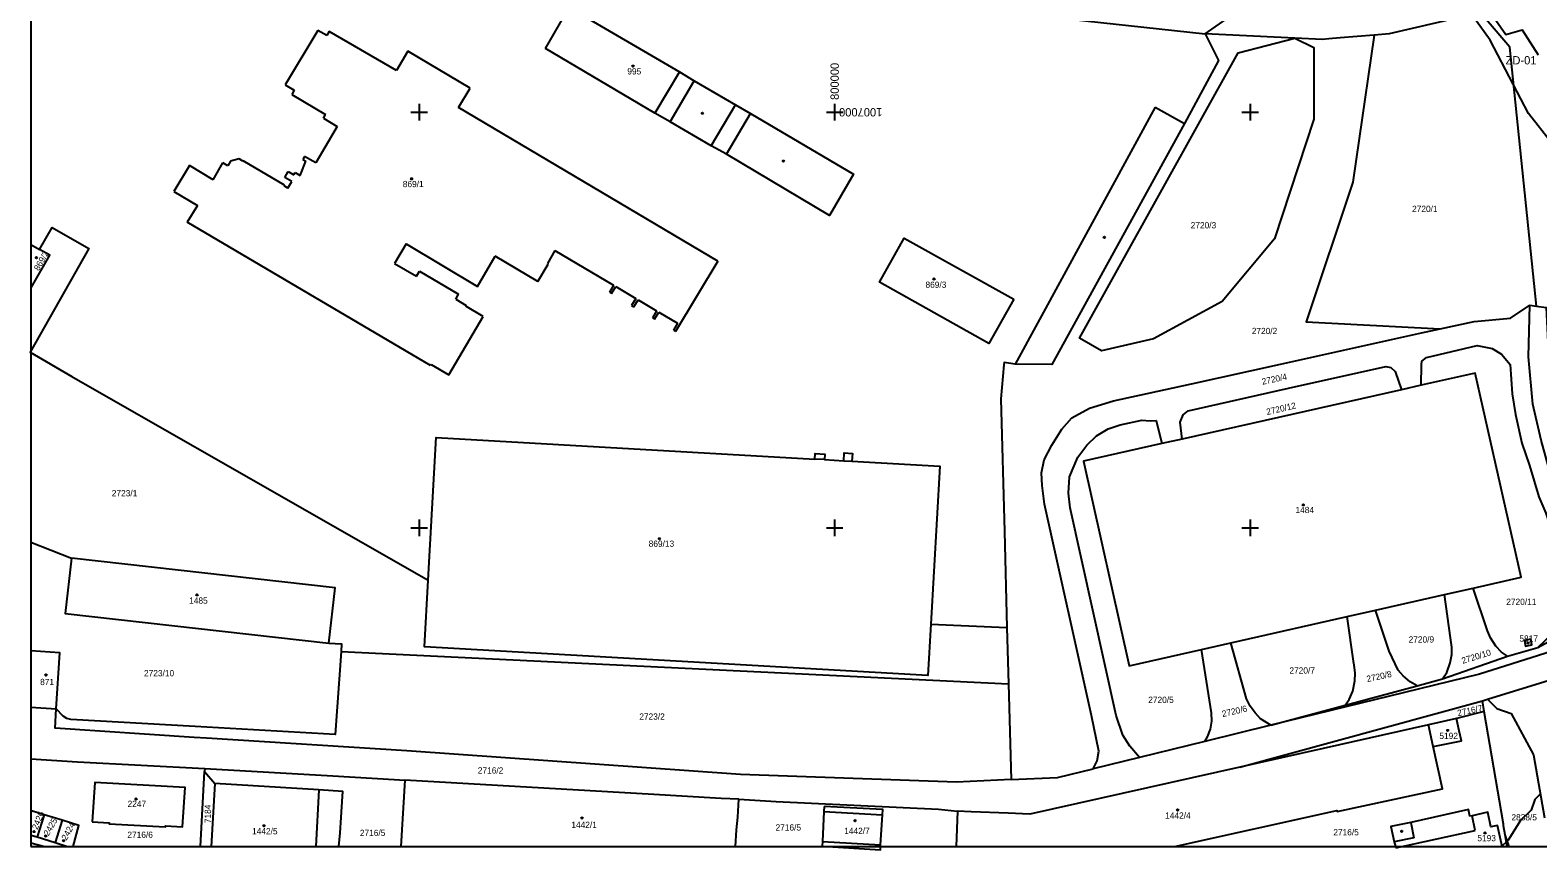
# Model space of a CAD drawing. Extents: x -800194 to -799297, y -1007177 to -1006761.
# Drawn here: x -800193.6 to -799830.8, y -1007177.4 to -1006980.2 of the extents above; entities that cross this region are included whole.
import ezdxf

# ---------------------------------------------------------------- set-up
doc = ezdxf.new("R2010")
doc.units = 0
for name, color, linetype in [('BPEJ', 7, 'Continuous'), ('Dočasné zábory', 7, 'Continuous'), ('Dočasné zábory - čísla', 7, 'Continuous'), ('Legenda 1', 7, 'Continuous'), ('Ramove udaje', 7, 'Continuous'), ('Vrstva 55', 7, 'Continuous'), ('Vrstva 56', 7, 'Continuous'), ('Vrstva 57', 7, 'Continuous'), ('Vrstva 59', 7, 'Continuous')]:
    doc.layers.add(name, color=color, linetype=linetype)

msp = doc.modelspace()

# ---------------------------------------------------------------- linework, layer by layer
at = {"layer": 'BPEJ'}
msp.add_lwpolyline([(-799830.18, -1007163.95), (-799831.53, -1007165.33), (-799832.38, -1007167.87), (-799834.92, -1007170.41), (-799837.89, -1007175.07), (-799838.13, -1007175.29), (-799838.36, -1007175.51), (-799839.39, -1007176.48), (-799839.57, -1007176.65)], dxfattribs=at)
at = {"layer": 'Dočasné zábory'}
for points in [[(-799851.52, -1006962.6), (-799838.48, -1006981.29), (-799834.59, -1006980.15), (-799830.67, -1006986.18)], [(-799827.49, -1007007.33), (-799833.05, -1007000.26), (-799842.29, -1006982.66), (-799850.11, -1006971.65)]]:
    msp.add_lwpolyline(points, dxfattribs=at)
at = {"layer": 'Legenda 1'}
msp.add_lwpolyline([(-800193.4, -1007176.65), (-799312.4, -1007176.65), (-799312.4, -1006766.65), (-800193.4, -1006766.65)], close=True, dxfattribs=at)
at = {"layer": 'Ramove udaje'}
for p, q in [((-800102, -1007000), (-800100, -1007000)), ((-800100, -1006998), (-800100, -1007002)), ((-800100, -1007000), (-800098, -1007000)), ((-800002, -1007000), (-800000, -1007000)), ((-800000, -1006998), (-800000, -1007002)), ((-800000, -1007000), (-799998, -1007000)), ((-799902, -1007000), (-799900, -1007000)), ((-799900, -1006998), (-799900, -1007002)), ((-799900, -1007000), (-799898, -1007000)), ((-800100, -1007098), (-800100, -1007102)), ((-800000, -1007098), (-800000, -1007102)), ((-799900, -1007098), (-799900, -1007102)), ((-800102, -1007100), (-800100, -1007100)), ((-800100, -1007100), (-800098, -1007100)), ((-800002, -1007100), (-800000, -1007100)), ((-800000, -1007100), (-799998, -1007100)), ((-799902, -1007100), (-799900, -1007100)), ((-799900, -1007100), (-799898, -1007100))]:
    msp.add_line(p, q, dxfattribs=at)
at = {"layer": 'Vrstva 55'}
for p, q in [((-799910.85, -1006981.15), (-799905.8, -1006977.56)), ((-799870.16, -1006981.42), (-799878.32, -1006982.12)), ((-799866.6, -1006981.12), (-799870.16, -1006981.42)), ((-799832.71, -1007046.42), (-799831.14, -1007046.62)), ((-799858.8, -1007053.02), (-799854.29, -1007052.07)), ((-799854.29, -1007052.07), (-799846.07, -1007050.35)), ((-799863.56, -1007066.73), (-799916.37, -1007078.61)), ((-799858.84, -1007065.67), (-799863.56, -1007066.73)), ((-799916.37, -1007078.61), (-799921.23, -1007079.7)), ((-799869.87, -1007119.78), (-799853.26, -1007116.03)), ((-799853.26, -1007116.03), (-799846.34, -1007114.47)), ((-799876.63, -1007121.3), (-799869.87, -1007119.78)), ((-799976.85, -1007123.12), (-799958.55, -1007123.98)), ((-799958.55, -1007123.98), (-799958.18, -1007137.5)), ((-799904.64, -1007127.61), (-799876.63, -1007121.3)), ((-799911.69, -1007129.2), (-799904.64, -1007127.61)), ((-800118.77, -1007129.72), (-799958.18, -1007137.5)), ((-799853.69, -1007136.27), (-799838.05, -1007130.83)), ((-799838.05, -1007130.83), (-799830.82, -1007128.75)), ((-799958.18, -1007137.5), (-799957.55, -1007160.54)), ((-799877.13, -1007142.66), (-799859.81, -1007137.94)), ((-799859.81, -1007137.94), (-799853.69, -1007136.27)), ((-799902.49, -1007157.51), (-799844.11, -1007141.59)), ((-799895.02, -1007147.45), (-799877.13, -1007142.66)), ((-799844.11, -1007141.59), (-799842.89, -1007141.21)), ((-799843.67, -1007144.18), (-799844.11, -1007141.59)), ((-799842.89, -1007141.21), (-799840.66, -1007143.43)), ((-800193.4, -1007143.13), (-800187.33, -1007143.52)), ((-799850.35, -1007145.84), (-799857.1, -1007147.35)), ((-799843.67, -1007144.18), (-799850.35, -1007145.84)), ((-799895.02, -1007147.45), (-799910.9, -1007151.34)), ((-799855.94, -1007152.6), (-799857.1, -1007147.35)), ((-799910.9, -1007151.34), (-799926.68, -1007155.21)), ((-799926.68, -1007155.21), (-799937.79, -1007157.93)), ((-799831.81, -1007154.54), (-799829.18, -1007169.73)), ((-800152.57, -1007176.65), (-800151.6, -1007158.62)), ((-800151.56, -1007157.89), (-800151.6, -1007158.62)), ((-800151.6, -1007158.62), (-800149.16, -1007161.51)), ((-800193.27, -1007168.03), (-800193.4, -1007168.44)), ((-800190.22, -1007168.97), (-800193.27, -1007168.03)), ((-800190.22, -1007168.97), (-800191.87, -1007174.32)), ((-800185.91, -1007170.3), (-800190.22, -1007168.97)), ((-800185.91, -1007170.3), (-800187.57, -1007175.65)), ((-800193.4, -1007173.88), (-800191.87, -1007174.32)), ((-800191.87, -1007174.32), (-800187.57, -1007175.65)), ((-799837.65, -1007176.65), (-799838.65, -1007173.83)), ((-800190.41, -1007176.65), (-800193.4, -1007175.83))]:
    msp.add_line(p, q, dxfattribs=at)
for points in [[(-800126.38, -1006954.46), (-800114.82, -1006956.57), (-800087.75, -1006960.99), (-799990.59, -1006972.38), (-799910.85, -1006981.15)], [(-800069.59, -1006984.65), (-800063.85, -1006974.82), (-800037.33, -1006990.25), (-800033.78, -1006992.42), (-800023.89, -1006998.18), (-800020.27, -1007000.33), (-799995.43, -1007014.87), (-800001.26, -1007024.83), (-800026.05, -1007010.11), (-800029.71, -1007008.06), (-800039.6, -1007002.32), (-800043.23, -1007000.2), (-800069.59, -1006984.65)], [(-799831.14, -1007046.62), (-799837.54, -1006984.31), (-799843.2, -1006977.69), (-799849.98, -1006977.29), (-799866.6, -1006981.12)], [(-799910.85, -1006981.15), (-799907.6, -1006987.58), (-799915.79, -1007002.7), (-799947.77, -1007060.68), (-799956.59, -1007060.62), (-799959.22, -1007060.2), (-799959.32, -1007060.77), (-799959.99, -1007068.95), (-799959.15, -1007100.86), (-799958.55, -1007123.98)], [(-799889.28, -1006982.17), (-799884.71, -1006984.4), (-799884.66, -1007001.67), (-799894.18, -1007030.47), (-799906.77, -1007045.52), (-799923.26, -1007054.52), (-799935.81, -1007057.35), (-799941.05, -1007054.37), (-799902.88, -1006985.7), (-799889.28, -1006982.17)], [(-799882.61, -1006982.49), (-799889.28, -1006982.17), (-799910.85, -1006981.15)], [(-799870.16, -1006981.42), (-799875.33, -1007016.85), (-799886.5, -1007050.4), (-799854.29, -1007052.07)], [(-799878.32, -1006982.12), (-799881.11, -1006982.36), (-799882.61, -1006982.49)], [(-800191.31, -1007032.99), (-800188.29, -1007027.72), (-800179.43, -1007032.73), (-800193.59, -1007057.69), (-800183.59, -1007063.53), (-800097.8, -1007112.58)], [(-799956.91, -1007044.98), (-799962.88, -1007055.62), (-799989.23, -1007040.87), (-799983.28, -1007030.28), (-799956.91, -1007044.98)], [(-800193.4, -1007031.8), (-800191.31, -1007032.99)], [(-800193.4, -1007041.97), (-800193.25, -1007042.05), (-800188.86, -1007034.38), (-800191.31, -1007032.99)], [(-799846.07, -1007050.35), (-799837.39, -1007049.52), (-799832.71, -1007046.42)], [(-799823.03, -1007089.38), (-799825.77, -1007089.63), (-799827.26, -1007088.72), (-799830.02, -1007078.85), (-799832.03, -1007070.18), (-799833.02, -1007058.82), (-799832.71, -1007046.42)], [(-799831.14, -1007046.62), (-799828.75, -1007046.93), (-799828.27, -1007056.97), (-799826.13, -1007070.87), (-799825.16, -1007076.77), (-799823.03, -1007089.38)], [(-799937.79, -1007157.93), (-799936.82, -1007156.03), (-799936.45, -1007153.7), (-799938.22, -1007145.09), (-799949.52, -1007094.24), (-799950.07, -1007089.8), (-799950.22, -1007086.71), (-799949.61, -1007083.61), (-799947.74, -1007080.12), (-799945.31, -1007076.24), (-799942.96, -1007073.53), (-799938.68, -1007071.19), (-799932.9, -1007069.42), (-799914.16, -1007065.36), (-799892.71, -1007060.59), (-799858.8, -1007053.02)], [(-799858.84, -1007065.67), (-799858.76, -1007060.77), (-799858.72, -1007059.86), (-799857.59, -1007058.97), (-799845.38, -1007056.13), (-799841.77, -1007056.79), (-799839.5, -1007058.21), (-799837.43, -1007060.68), (-799836.99, -1007067.77), (-799836.14, -1007072.71), (-799834.61, -1007079.6), (-799832.83, -1007084.94), (-799830.58, -1007092.52), (-799828.9, -1007096.44), (-799827.32, -1007101.2), (-799825.89, -1007106.02), (-799824.52, -1007111.92), (-799824.25, -1007121.19), (-799824.17, -1007122.98), (-799825.87, -1007124.09), (-799830.82, -1007128.75)], [(-799916.37, -1007078.61), (-799916.82, -1007074.54), (-799916.17, -1007072.79), (-799914.91, -1007071.85), (-799890.76, -1007066.36), (-799867.37, -1007061.12), (-799866.17, -1007061.36), (-799865.15, -1007062.35), (-799863.56, -1007066.73)], [(-799846.34, -1007114.47), (-799834.79, -1007111.87), (-799845.89, -1007062.76), (-799858.84, -1007065.67)], [(-799926.68, -1007155.21), (-799928.97, -1007152.5), (-799930.66, -1007149.85), (-799932.29, -1007145.14), (-799943.36, -1007095.14), (-799943.76, -1007091.6), (-799943.45, -1007087.73), (-799941.48, -1007082.96), (-799939.34, -1007080.12), (-799936.97, -1007077.8), (-799934.15, -1007076.19), (-799931.27, -1007075.17), (-799926.04, -1007074.1), (-799924.08, -1007074.23), (-799922.66, -1007074.11), (-799921.23, -1007079.7)], [(-800097.8, -1007112.58), (-800095.87, -1007078.26), (-800004.78, -1007083.43), (-800004.71, -1007082.11), (-800002.37, -1007082.25), (-800002.45, -1007083.56), (-799997.79, -1007083.83), (-799997.69, -1007081.95), (-799995.74, -1007082.06), (-799995.86, -1007083.94), (-799974.69, -1007085.14), (-799976.85, -1007123.12)], [(-799921.23, -1007079.7), (-799940.15, -1007083.96), (-799929.14, -1007133.13), (-799911.69, -1007129.2)], [(-799830.82, -1007128.75), (-799819.06, -1007122.35), (-799820.88, -1007108.46), (-799823.65, -1007098.62), (-799823.55, -1007095.54), (-799822.31, -1007094.44)], [(-800193.4, -1007103.43), (-800183.62, -1007107.27)], [(-800183.62, -1007107.27), (-800185.18, -1007120.54), (-800121.74, -1007127.7)], [(-800121.74, -1007127.7), (-800120.18, -1007114.39), (-800183.62, -1007107.27)], [(-799976.85, -1007123.12), (-799977.55, -1007135.46), (-800098.7, -1007128.56), (-800097.8, -1007112.58)], [(-799853.69, -1007136.27), (-799852.72, -1007134.73), (-799851.85, -1007132.41), (-799851.49, -1007130.4), (-799851.51, -1007128.69), (-799851.8, -1007126.44), (-799853.26, -1007116.03)], [(-799838.05, -1007130.83), (-799839.52, -1007129.85), (-799840.91, -1007128.4), (-799842.17, -1007126.45), (-799842.9, -1007124.78), (-799846.34, -1007114.47)], [(-799859.81, -1007137.94), (-799861.51, -1007136.99), (-799863.16, -1007135.61), (-799864.37, -1007134.2), (-799866.53, -1007129.66), (-799869.87, -1007119.78)], [(-799877.13, -1007142.66), (-799876.18, -1007141.27), (-799875.3, -1007139.22), (-799874.85, -1007136.77), (-799874.75, -1007134.96), (-799875, -1007132.95), (-799875.06, -1007132.59), (-799876.63, -1007121.3)], [(-800121.74, -1007127.7), (-800118.64, -1007127.9), (-800118.77, -1007129.72)], [(-799895.02, -1007147.45), (-799897.49, -1007145.93), (-799898.84, -1007144.45), (-799900.01, -1007142.86), (-799900.88, -1007141.07), (-799904.64, -1007127.61)], [(-799814.24, -1007125.43), (-799822.76, -1007128.21), (-799844.82, -1007135.16), (-799895.02, -1007147.45)], [(-799832.49, -1007126.78), (-799834.01, -1007127.06), (-799833.76, -1007128.46), (-799832.24, -1007128.15), (-799832.49, -1007126.78)], [(-800187.33, -1007143.52), (-800186.47, -1007130.03), (-800193.4, -1007129.55)], [(-800118.77, -1007129.72), (-800120.23, -1007149.7), (-800153.92, -1007147.78), (-800183.84, -1007146.08), (-800184.79, -1007145.86), (-800185.65, -1007145.24), (-800187.33, -1007143.52)], [(-799910.9, -1007151.34), (-799910.28, -1007150.28), (-799909.58, -1007148.38), (-799909.26, -1007146.44), (-799909.31, -1007144.47), (-799911.69, -1007129.2)], [(-799842.89, -1007141.21), (-799820.76, -1007134.4), (-799819.2, -1007134.15)], [(-799957.55, -1007160.54), (-799970.7, -1007161.15), (-800022.66, -1007159.29), (-800102.95, -1007153.65), (-800151.15, -1007150.56), (-800154.11, -1007150.37), (-800187.59, -1007148.16), (-800187.33, -1007143.52)], [(-799855.94, -1007152.6), (-799849.17, -1007151.19), (-799849.68, -1007148.8), (-799850.35, -1007145.84)], [(-799838.65, -1007173.83), (-799839.02, -1007171.64), (-799839.09, -1007171.24), (-799843.67, -1007144.18)], [(-799840.66, -1007143.43), (-799837.23, -1007144.63), (-799831.81, -1007154.54)], [(-799857.1, -1007147.35), (-799882.44, -1007153.02), (-799902.49, -1007157.51)], [(-799918.24, -1007176.65), (-799879.14, -1007167.97), (-799879.08, -1007168.21), (-799853.7, -1007162.72), (-799855.94, -1007152.6)], [(-800193.4, -1007155.51), (-800182.23, -1007156.22), (-800151.56, -1007157.89)], [(-799902.49, -1007157.51), (-799953, -1007168.82), (-799958.28, -1007168.59), (-799967.15, -1007168.25), (-799970.47, -1007168.12)], [(-800151.56, -1007157.89), (-800120.77, -1007159.66), (-800105.97, -1007160.48), (-800103.43, -1007160.63)], [(-800103.43, -1007160.63), (-800104.39, -1007176.65)], [(-800023.08, -1007165.28), (-800027.33, -1007165.05), (-800028.66, -1007164.97), (-800043.53, -1007164.15), (-800103.43, -1007160.63)], [(-799957.55, -1007160.54), (-799946.38, -1007160.03), (-799937.79, -1007157.93)], [(-800178.68, -1007170.71), (-800174.59, -1007170.94), (-800174.6, -1007171.19), (-800161.02, -1007171.93), (-800161, -1007171.68), (-800156.91, -1007171.91), (-800156.3, -1007162.43), (-800178.06, -1007161.23), (-800178.68, -1007170.71)], [(-800149.16, -1007161.51), (-800150.05, -1007176.65)], [(-800119.28, -1007176.65), (-800119, -1007173.34), (-800118.76, -1007169.65), (-800118.69, -1007168.26), (-800118.33, -1007163.39), (-800124.09, -1007162.99), (-800149.16, -1007161.51)], [(-800193.27, -1007168.03), (-800193.4, -1007167.99)], [(-800023.85, -1007176.65), (-800023.63, -1007172.6), (-800023.3, -1007169.57), (-800023.08, -1007165.28)], [(-800023.08, -1007165.28), (-800014.06, -1007165.81), (-799975.01, -1007167.61), (-799970.47, -1007168.12)], [(-800002.51, -1007167.02), (-800002.58, -1007168.18), (-800002.95, -1007175.44), (-800003, -1007176.58), (-799988.98, -1007177.43), (-799988.93, -1007176.25), (-799988.52, -1007168.97), (-799988.43, -1007167.73), (-800002.51, -1007167.02)], [(-799970.47, -1007168.12), (-799970.77, -1007176.65)], [(-799839.36, -1007176.65), (-799840.49, -1007171.57), (-799842.09, -1007171.9), (-799842.85, -1007168.35), (-799846.6, -1007169.23), (-799847.19, -1007169.37), (-799847.51, -1007167.75), (-799861.36, -1007170.85), (-799866.14, -1007171.83), (-799865.33, -1007175.48), (-799865.03, -1007176.65)], [(-800183.26, -1007176.65), (-800181.9, -1007171.54), (-800185.91, -1007170.3)], [(-800187.57, -1007175.65), (-800184.62, -1007176.65)], [(-799838.17, -1007176.65), (-799838.65, -1007173.83)]]:
    msp.add_lwpolyline(points, dxfattribs=at)
at = {"layer": 'Vrstva 56'}
for p, q in [((-800124.35, -1006980.32), (-800132.2, -1006993.41)), ((-800122.19, -1006981.56), (-800124.35, -1006980.32)), ((-800121.6, -1006980.54), (-800122.19, -1006981.56)), ((-800105.43, -1006989.93), (-800121.6, -1006980.54)), ((-800102.67, -1006985.33), (-800105.43, -1006989.93)), ((-800087.72, -1006994.21), (-800102.67, -1006985.33)), ((-800037.33, -1006990.25), (-800043.23, -1007000.2)), ((-800132.2, -1006993.41), (-800130.02, -1006994.7)), ((-800090.55, -1006998.86), (-800087.72, -1006994.21)), ((-800039.6, -1007002.32), (-800033.78, -1006992.42)), ((-800130.02, -1006994.7), (-800130.63, -1006995.76)), ((-800130.63, -1006995.76), (-800122.52, -1007000.52)), ((-800123.04, -1007001.41), (-800122.52, -1007000.52)), ((-800123.04, -1007001.41), (-800119.68, -1007003.41)), ((-800028.13, -1007035.85), (-800090.55, -1006998.86)), ((-800029.71, -1007008.06), (-800023.89, -1006998.18)), ((-800026.05, -1007010.11), (-800020.27, -1007000.33)), ((-799922.84, -1006998.8), (-799956.59, -1007060.62)), ((-799922.84, -1006998.8), (-799915.79, -1007002.7)), ((-800119.68, -1007003.41), (-800124.85, -1007012.2)), ((-800149.57, -1007016.23), (-800147.2, -1007012.17)), ((-800146.02, -1007012.87), (-800147.2, -1007012.17)), ((-800145.37, -1007011.77), (-800146.02, -1007012.87)), ((-800143.33, -1007011.23), (-800145.37, -1007011.77)), ((-800142.4, -1007011.79), (-800143.33, -1007011.23)), ((-800142.32, -1007011.66), (-800142.4, -1007011.79)), ((-800132.41, -1007017.55), (-800142.32, -1007011.66)), ((-800128.59, -1007015.24), (-800127.23, -1007011.79)), ((-800127.54, -1007010.61), (-800127.98, -1007011.36)), ((-800127.98, -1007011.36), (-800127.23, -1007011.79)), ((-800124.85, -1007012.2), (-800127.54, -1007010.61)), ((-800155.27, -1007012.78), (-800159.02, -1007019.05)), ((-800149.57, -1007016.23), (-800155.27, -1007012.78)), ((-800132.31, -1007015.7), (-800131.47, -1007014.23)), ((-800130.66, -1007016.65), (-800132.31, -1007015.7)), ((-800131.47, -1007014.23), (-800130.11, -1007015.01)), ((-800130.11, -1007015.01), (-800129.82, -1007014.51)), ((-800129.82, -1007014.51), (-800128.59, -1007015.24)), ((-800159.02, -1007019.05), (-800153.33, -1007022.41)), ((-800132.49, -1007017.68), (-800132.41, -1007017.55)), ((-800131.56, -1007018.23), (-800132.49, -1007017.68)), ((-800131.56, -1007018.23), (-800130.66, -1007016.65)), ((-800153.33, -1007022.41), (-800155.77, -1007026.42)), ((-800097.23, -1007060.91), (-800155.77, -1007026.42)), ((-800103.14, -1007031.67), (-800105.89, -1007036.34)), ((-800103.14, -1007031.67), (-800085.96, -1007041.88)), ((-800067.3, -1007033.22), (-800069.13, -1007036.39)), ((-800067.3, -1007033.22), (-800053.2, -1007041.6)), ((-800105.89, -1007036.34), (-800100.61, -1007039.41)), ((-800085.96, -1007041.88), (-800081.71, -1007034.61)), ((-800071.42, -1007040.72), (-800081.71, -1007034.61)), ((-800071.42, -1007040.72), (-800068.9, -1007036.53)), ((-800069.13, -1007036.39), (-800068.9, -1007036.53)), ((-800028.13, -1007035.85), (-800038.26, -1007052.73)), ((-800100.61, -1007039.41), (-800099.92, -1007038.25)), ((-800099.92, -1007038.25), (-800090.48, -1007043.75)), ((-800091.15, -1007044.99), (-800090.48, -1007043.75)), ((-800091.15, -1007044.99), (-800088.64, -1007046.47)), ((-800053.2, -1007041.6), (-800054.21, -1007043.3)), ((-800054.21, -1007043.3), (-800053.66, -1007043.63)), ((-800053.66, -1007043.63), (-800052.65, -1007041.93)), ((-800052.65, -1007041.93), (-800047.84, -1007044.78)), ((-800047.84, -1007044.78), (-800048.85, -1007046.49)), ((-800088.64, -1007046.47), (-800088.75, -1007046.65)), ((-800084.56, -1007049.14), (-800088.75, -1007046.65)), ((-800048.85, -1007046.49), (-800048.31, -1007046.81)), ((-800048.31, -1007046.81), (-800047.3, -1007045.11)), ((-800047.3, -1007045.11), (-800042.85, -1007047.75)), ((-800042.85, -1007047.75), (-800043.86, -1007049.45)), ((-800043.31, -1007049.78), (-800042.3, -1007048.08)), ((-800042.3, -1007048.08), (-800037.79, -1007050.75)), ((-800092.88, -1007063.2), (-800084.56, -1007049.14)), ((-800043.86, -1007049.45), (-800043.31, -1007049.78)), ((-800037.79, -1007050.75), (-800038.8, -1007052.45)), ((-800038.8, -1007052.45), (-800038.26, -1007052.73)), ((-800097.11, -1007060.7), (-800097.23, -1007060.91)), ((-800097.11, -1007060.7), (-800092.88, -1007063.2)), ((-800002.45, -1007083.56), (-800004.78, -1007083.43)), ((-799997.79, -1007083.83), (-799995.86, -1007083.94)), ((-800124.09, -1007162.99), (-800124.88, -1007176.65)), ((-800002.58, -1007168.18), (-799988.52, -1007168.97)), ((-799861.36, -1007170.85), (-799860.6, -1007174.51)), ((-799845.85, -1007172.76), (-799846.6, -1007169.23)), ((-800002.95, -1007175.44), (-799988.93, -1007176.25)), ((-799860.6, -1007174.51), (-799865.33, -1007175.48)), ((-799864.94, -1007176.98), (-799845.85, -1007172.76))]:
    msp.add_line(p, q, dxfattribs=at)
at = {"layer": 'Vrstva 59'}
for centre in [(-800048.53, -1006988.9), (-800031.82, -1007000.23), (-800012.33, -1007011.74), (-800101.81, -1007016.01), (-799935.1, -1007030.07), (-800192.07, -1007034.96), (-799976.08, -1007040.1), (-799887.24, -1007094.44), (-800042.17, -1007102.59), (-800153.45, -1007116.09), (-799833.12, -1007127.69), (-800189.79, -1007135.38), (-799852.47, -1007148.71), (-800168.1, -1007165.2), (-799917.46, -1007167.86), (-800137.35, -1007171.65), (-800060.79, -1007169.78), (-799995.07, -1007170.42), (-800192.64, -1007173.04), (-800189.84, -1007174.1), (-800185.52, -1007175.25), (-799863.53, -1007172.98), (-799843.49, -1007173.35)]:
    msp.add_circle(centre, 0.175, dxfattribs=at)

# ---------------------------------------------------------------- texts
at = {"layer": 'Dočasné zábory - čísla'}
msp.add_text('ZD-01', height=2, rotation=0, dxfattribs=at).set_placement((-799838.54, -1006988.49))
at = {"layer": 'Ramove udaje'}
for s, rotation, p in [('    800000', 90, (-799999, -1007000)), ('1007000    ', 180, (-799988.53, -1006999))]:
    msp.add_text(s, height=2, rotation=rotation, dxfattribs=at).set_placement(p)
at = {"layer": 'Vrstva 57'}
for s, p in [('995', (-800049.89, -1006990.9)), ('869/1', (-800103.92, -1007018.01)), ('2720/1', (-799861.05, -1007023.98)), ('2720/3', (-799914.32, -1007027.93)), ('869/3', (-799978.14, -1007042.23)), ('2720/2', (-799899.63, -1007053.36)), ('2723/1', (-800173.94, -1007092.37)), ('1484', (-799889.11, -1007096.42)), ('869/13', (-800044.75, -1007104.53)), ('1485', (-800155.33, -1007118.22)), ('2720/11', (-799838.38, -1007118.5)), ('2720/9', (-799861.88, -1007127.57)), ('5817', (-799835.22, -1007127.35)), ('2723/10', (-800166.19, -1007135.68)), ('2720/7', (-799890.56, -1007135.03)), ('871', (-800191.19, -1007137.8)), ('2720/5', (-799924.54, -1007142.09)), ('2723/2', (-800047.01, -1007146.12)), ('5192', (-799854.48, -1007150.76)), ('2716/2', (-800085.86, -1007159.07)), ('2247', (-800170.14, -1007167.11)), ('1442/4', (-799920.46, -1007169.93)), ('1442/1', (-800063.36, -1007172.16)), ('2716/5', (-800014.22, -1007172.79)), ('1442/7', (-799997.7, -1007173.63)), ('2838/5', (-799837.14, -1007170.35)), ('2716/6', (-800170.19, -1007174.55)), ('1442/5', (-800140.19, -1007173.7)), ('2716/5', (-800114.25, -1007174.11)), ('2716/5', (-799880, -1007173.95)), ('5193', (-799845.34, -1007175.36))]:
    msp.add_text(s, height=1.5, dxfattribs=at).set_placement(p)
for s, rotation, p in [('869/2', 60.2504, (-800191.5, -1007038.27)), ('2720/4', 12, (-799897.04, -1007065.56)), ('2720/12', 13, (-799895.93, -1007072.84)), ('2720/10', 17, (-799848.86, -1007132.7)), ('2720/8', 12, (-799871.84, -1007137.09)), ('2720/6', 13, (-799906.61, -1007145.49)), ('2716/7', 12, (-799849.99, -1007145.29)), ('2426', 68, (-800191.84, -1007172.68)), ('7184', 91, (-800150.06, -1007171.01)), ('2425', 60, (-800189.18, -1007174.2)), ('2424', 61, (-800184.85, -1007175.27))]:
    msp.add_text(s, height=1.5, rotation=rotation, dxfattribs=at).set_placement(p)

doc.saveas('drawing.dxf')
